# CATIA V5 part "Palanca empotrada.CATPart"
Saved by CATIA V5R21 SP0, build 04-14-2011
Part number: Palanca empotrada
Material "Steel": density 7860 kg/m3, Young's modulus 2e+11 Pa, Poisson ratio 0.266, thermal expansion 1.17e-05 1/K
Bounding box of the stored display mesh (mm): x -50.8 to 381, y 0 to 457.2, z -19.05 to 19.05
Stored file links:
  C:\Users\David\Desktop\TFG\catia\Palanca empotrada.CATPart
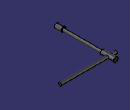
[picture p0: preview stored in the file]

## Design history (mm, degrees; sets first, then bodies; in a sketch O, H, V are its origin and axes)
Body1 (main body), material "Steel"
  Sketch1 on zx-plane, origin (0, 0, 0), H (0, 0, 1), V (-1, 0, 0)
    circle A1 centre (0, 0) radius 19.05
    radius A1 = 19.05
  Pad1: profile Sketch1, direction (0, 1, 0), length 50.8
  Sketch2 on xy-plane, origin (0, 0, 0), H (1, 0, 0), V (0, 1, 0)
    reference projected line E1 (19.05, 50.8) -> (-19.05, 50.8) from edge [end face of Pad1 | face of Pad1 from Sketch1.A1]
    construction line L1 (-12.7, 0) -> (-12.7, 67.3634)
    point P3 (-12.7, 0)
    reference projected line E2 through (0, 0) direction (0, -1) from axis of face of Pad1 from Sketch1.A1
    line L2 (-12.7, 53.975) -> (0, 53.975)
    point P5 (-12.7, 53.975)
    point P6 (0, 53.975)
    construction line L3 (-12.7, 53.975) -> (-15.875, 53.975)
    arc A1 centre (-15.875, 53.975) radius 3.175 from (-15.875, 50.8) to (-12.7, 53.975) ccw
    point P8 (-15.875, 50.8)
    line L4 (0, 53.975) -> (0, 50.8)
    point P9 (0, 50.8)
    line L5 (-15.875, 50.8) -> (0, 50.8)
    distance E2 L1 = 12.7
    length L3 = 3.175
    coincidence: P3 H, P5 L1, P6 V, P8 E1
    vertical: L1 V, L4 V
    horizontal: L2 H, L3 H
    tangency: A1 L1, L5 A1
    midpoint: P9 E1
  Shaft1: profile Sketch2, axis axis of face of Pad1 from Sketch1.A1, angle 180
  Mirror1: of the body so far, about xy-plane
  Sketch3 on face of Shaft1, origin (0, 53.975, 0), H (0, 0, 1), V (-1, 0, 0)
    circle A1 centre (0, 0) radius 12.7
    radius A1 = 12.7
  Pad2: profile Sketch3, direction (0, 1, 0), length 301.625
  Sketch4 on end face of Pad2, origin (0, 355.6, 0), H (-1, 0, 0), V (0, 0, 1)
    circle A1 centre (0, 0) radius 19.05
    point P1 (0, 19.05)
    radius A1 = 19.05
    coincidence: A1 P1, P1 V
  Pad3: profile Sketch4, direction (0, 1, 0), length 101.6
  Sketch5 on yz-plane, origin (0, 0, 0), H (0, 1, 0), V (0, 0, 1)
    circle A1 centre (406.4, 0) radius 12.7
    point P1 (406.4, 0)
    radius A1 = 12.7
    distance P1 V = 406.4
    coincidence: P1 H
  Pad4: profile Sketch5, direction (1, 0, 0), length 381
  Sketch6 on yz-plane, origin (0, 0, 0), H (0, 1, 0), V (0, 0, 1)
    projected circle E1 centre (406.4, 0) radius 12.7 from edge [face of Pad4 from Sketch5.A1 | end face of Pad4]
  Pad5: profile Sketch6, direction (-1, 0, 0), length 50.8
  Point1: (381, 406.4, 12.7)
